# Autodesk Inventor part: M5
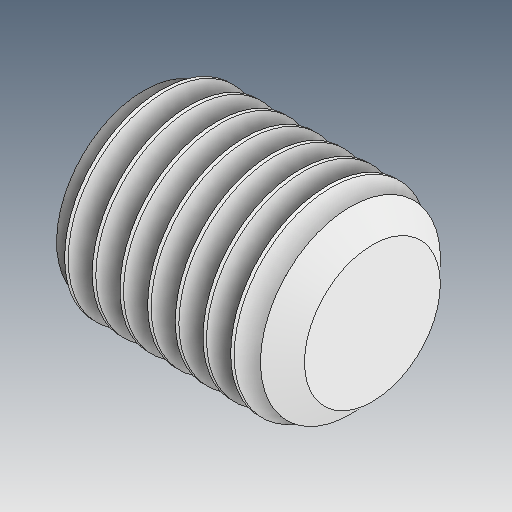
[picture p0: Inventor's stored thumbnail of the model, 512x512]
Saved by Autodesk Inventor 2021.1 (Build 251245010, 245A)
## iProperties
Created: 2021-05
Part Number: M5
Material: Ogólny
Document SubType Name: Modeling
Designer: user
Density: 1 g/cm^3
Appearance: Domyślna
Author: user
Revision Number: ÈÎºÎ
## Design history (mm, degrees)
feature "ÊäÈë1"
node "Bryła1"
